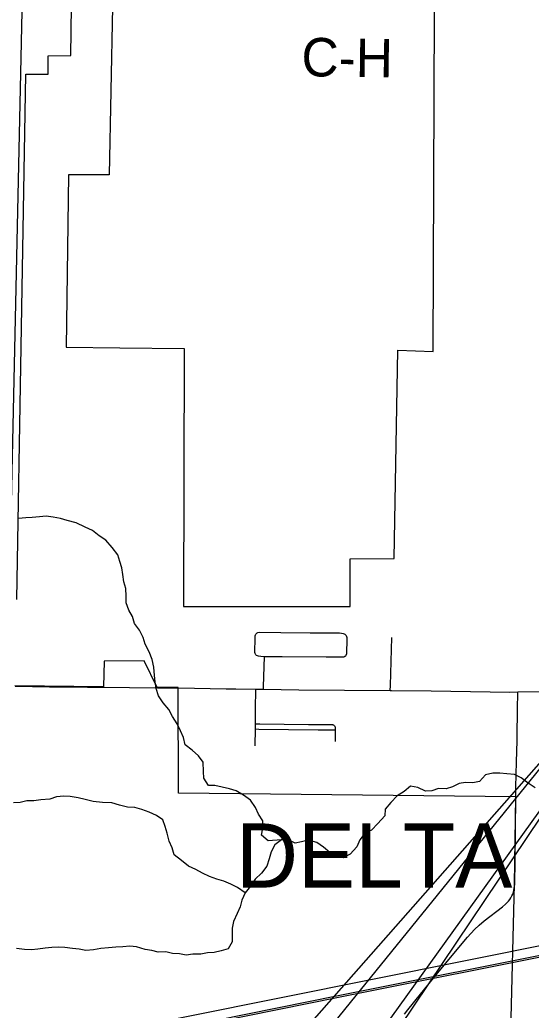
# Model space of a CAD drawing. Extents: x -21.7 to 34, y 0 to 22.
# Drawn here: x 25.914 to 26.67, y 17.008 to 18.47 of the extents above; entities that cross this region are included whole.
import ezdxf

# ---------------------------------------------------------------- set-up
doc = ezdxf.new("R2010")
doc.units = 0
for name, color, linetype in [('GM_X_City_Street', 7, 'Continuous'), ('GM_X_Corporation', 7, 'Continuous'), ('GM_X_Corporation_Text', 7, 'Continuous'), ('GM_X_County_Road', 7, 'Continuous'), ('GM_X_County_Road_Text', 7, 'Continuous'), ('GM_X_Minor_River', 7, 'Continuous'), ('GM_X_Rail_Line', 7, 'Continuous'), ('GM_X_State_Route', 7, 'Continuous'), ('GM_X_US_Route', 7, 'Continuous'), ('SH_Text', 7, 'Continuous')]:
    doc.layers.add(name, color=color, linetype=linetype)

msp = doc.modelspace()

# ---------------------------------------------------------------- linework, layer by layer
at = {"layer": 'GM_X_City_Street'}
msp.add_line((26.2622, 17.3982), (26.2624, 17.4229), dxfattribs=at)
for points in [[(26.2759, 17.5296), (26.2703, 17.5299), (26.267, 17.5305), (26.2655, 17.5309), (26.2641, 17.5315), (26.2632, 17.5323), (26.2625, 17.5333), (26.2619, 17.5345), (26.2617, 17.5356), (26.2615, 17.5373), (26.2614, 17.5403), (26.2618, 17.5529), (26.262, 17.559), (26.2622, 17.5605), (26.2626, 17.5619), (26.2631, 17.563), (26.2639, 17.5641), (26.2647, 17.5648), (26.266, 17.5654), (26.2688, 17.5658), (26.2998, 17.5655), (26.3432, 17.5649), (26.3772, 17.5647), (26.3865, 17.5648), (26.3896, 17.5646), (26.3922, 17.5641), (26.3934, 17.5636), (26.3944, 17.5629), (26.3962, 17.5608), (26.3968, 17.5596), (26.3972, 17.5582), (26.3974, 17.5551), (26.3969, 17.535), (26.3967, 17.5334), (26.3966, 17.5327), (26.3961, 17.5314), (26.3952, 17.5304), (26.3944, 17.5297), (26.393, 17.5291), (26.3917, 17.5289), (26.3887, 17.5288), (26.367, 17.5289), (26.3021, 17.5294), (26.2759, 17.5296)], [(26.4615, 17.4797), (26.4617, 17.4869), (26.4639, 17.558)], [(26.2741, 17.4816), (26.2742, 17.4856), (26.2759, 17.5296)], [(26.2625, 17.4305), (26.2627, 17.4578), (26.2629, 17.4763), (26.2629, 17.4818)], [(26.2624, 17.4229), (26.2625, 17.4238), (26.2625, 17.4305)], [(26.2625, 17.4305), (26.2691, 17.4304), (26.3409, 17.4296), (26.3753, 17.4295), (26.3762, 17.4294), (26.3768, 17.4292), (26.3776, 17.4289), (26.3782, 17.4285), (26.3788, 17.428), (26.3793, 17.4274), (26.3797, 17.4267), (26.38, 17.4261), (26.3802, 17.4253), (26.3803, 17.4245), (26.3804, 17.423), (26.3804, 17.4217)], [(26.2624, 17.4229), (26.2672, 17.4228), (26.3553, 17.4217), (26.3742, 17.4217), (26.3804, 17.4217)], [(26.3804, 17.4217), (26.3803, 17.4199), (26.3802, 17.4043)]]:
    msp.add_lwpolyline(points, dxfattribs=at)
at = {"layer": 'GM_X_Corporation'}
for points in [[(25.9101, 17.6139), (25.9163, 17.9873), (25.9231, 18.3896), (25.956, 18.3896), (25.9564, 18.4169), (25.9895, 18.4172), (25.9908, 18.4897)], [(26.0513, 18.4893), (26.0461, 18.2409), (25.9862, 18.2409), (25.9829, 17.9866), (26.062, 17.9857), (26.1572, 17.9846), (26.1563, 17.6036), (26.4021, 17.6038), (26.4021, 17.6743), (26.4675, 17.6744), (26.4727, 17.982), (26.5248, 17.9802), (26.527, 18.482)], [(26.6397, 16.9761), (26.6452, 17.1938), (26.6469, 17.3226), (26.1489, 17.3283), (26.1483, 17.4841), (26.1174, 17.4842), (26.098, 17.5236), (26.0387, 17.5231), (26.0379, 17.485), (25.9072, 17.4864)]]:
    msp.add_lwpolyline(points, dxfattribs=at)
at = {"layer": 'GM_X_County_Road'}
for points in [[(26.6471, 17.322), (26.6472, 17.337), (26.6481, 17.3743), (26.6489, 17.4054), (26.6496, 17.4582), (26.6499, 17.4707), (26.6501, 17.4776)], [(26.6455, 17.1932), (26.6457, 17.1971), (26.6462, 17.2251), (26.6471, 17.322)], [(26.4827, 17.0017), (26.4876, 17.0083), (26.5063, 17.0315), (26.532, 17.0627), (26.5557, 17.0916), (26.5758, 17.1154), (26.5862, 17.1269), (26.593, 17.1334), (26.6001, 17.1395), (26.6272, 17.1604), (26.6319, 17.1645), (26.6361, 17.1689), (26.638, 17.1713), (26.6397, 17.1738), (26.6412, 17.1764), (26.6424, 17.1792), (26.6435, 17.182), (26.6443, 17.185), (26.6453, 17.191), (26.6455, 17.1932)]]:
    msp.add_lwpolyline(points, dxfattribs=at)
at = {"layer": 'GM_X_Minor_River'}
for points in [[(26.3007, 17.2591), (26.281, 17.2577), (26.2713, 17.2662), (26.2731, 17.2764), (26.2733, 17.2871), (26.2671, 17.2971), (26.2624, 17.307), (26.2551, 17.3178), (26.245, 17.3253), (26.2341, 17.3316), (26.2243, 17.3345), (26.2024, 17.3395), (26.193, 17.3397), (26.186, 17.3501), (26.1855, 17.36), (26.1854, 17.3737), (26.1784, 17.3833), (26.1688, 17.3915), (26.1587, 17.3997), (26.1559, 17.4104), (26.1516, 17.42), (26.1469, 17.4303), (26.14, 17.4415), (26.1345, 17.4515), (26.126, 17.4615), (26.1194, 17.4719), (26.1159, 17.4826), (26.1142, 17.4925), (26.1133, 17.5021), (26.1121, 17.5142), (26.1097, 17.5253), (26.1054, 17.5368), (26.0996, 17.5479), (26.0964, 17.5582), (26.0913, 17.569), (26.0836, 17.5786), (26.0808, 17.5889), (26.0753, 17.5985), (26.0714, 17.6093), (26.0713, 17.6188), (26.0708, 17.6302), (26.068, 17.6401), (26.0663, 17.6511), (26.065, 17.6606), (26.0622, 17.6702), (26.059, 17.6798), (26.0506, 17.691), (26.0413, 17.7018), (26.0316, 17.7081), (26.0216, 17.7159), (26.0107, 17.7211), (25.9975, 17.7271), (25.9843, 17.7308), (25.9742, 17.7337), (25.9636, 17.7354), (25.9534, 17.7372), (25.9435, 17.7362), (25.9328, 17.735), (25.923, 17.7348), (25.9123, 17.7335)], [(26.6755, 17.3358), (26.6654, 17.3428), (26.655, 17.3506), (26.6452, 17.3558), (26.6338, 17.3568), (26.6236, 17.3578), (26.613, 17.3576), (26.6023, 17.3552), (26.5934, 17.3456), (26.5835, 17.3435), (26.5728, 17.3441), (26.5633, 17.3424), (26.5537, 17.3377), (26.5442, 17.3345), (26.5328, 17.3348), (26.5229, 17.3316), (26.5134, 17.331), (26.5021, 17.3366), (26.4915, 17.3384), (26.4819, 17.3306), (26.4718, 17.3244), (26.4625, 17.3143), (26.4539, 17.3047), (26.4533, 17.2948), (26.4432, 17.2836), (26.4339, 17.2736), (26.4243, 17.2696), (26.4165, 17.2592), (26.412, 17.2487), (26.4023, 17.2382), (26.3919, 17.2328), (26.3821, 17.2353), (26.3724, 17.2404), (26.3627, 17.2482), (26.353, 17.2553), (26.3406, 17.259), (26.3306, 17.2562), (26.3211, 17.2545)], [(26.2473, 17.181), (26.236, 17.1888), (26.226, 17.1936), (26.2158, 17.198), (26.2053, 17.2013), (26.1944, 17.2053), (26.1843, 17.2101), (26.1741, 17.2153), (26.1633, 17.2204), (26.1532, 17.2286), (26.1424, 17.2372), (26.1396, 17.2475), (26.1349, 17.2575), (26.1321, 17.269), (26.1289, 17.2789), (26.1258, 17.2888), (26.116, 17.2951), (26.1055, 17.2999), (26.0946, 17.304), (26.0841, 17.3069), (26.0735, 17.3075), (26.0618, 17.3104), (26.0501, 17.3137), (26.0364, 17.3144), (26.0228, 17.3158), (26.0111, 17.3187), (26.0006, 17.3212), (25.9889, 17.3234), (25.9794, 17.3236), (25.9683, 17.3227), (25.9588, 17.3195), (25.9455, 17.3183), (25.9352, 17.317), (25.9246, 17.3169), (25.9147, 17.3144), (25.9048, 17.3139)], [(26.3211, 17.2545), (26.311, 17.2593), (26.3007, 17.2591), (26.2911, 17.2521), (26.2855, 17.2416), (26.2826, 17.2311), (26.2793, 17.2205), (26.2715, 17.21), (26.2618, 17.2012), (26.2551, 17.1907), (26.2473, 17.181), (26.2425, 17.1701), (26.2396, 17.1603), (26.2352, 17.1505), (26.23, 17.1389), (26.2279, 17.1287), (26.228, 17.118), (26.2282, 17.1085), (26.2219, 17.0984), (26.2116, 17.0952), (26.2016, 17.0928), (26.1914, 17.0923), (26.1815, 17.0902), (26.1701, 17.0905), (26.1602, 17.0888), (26.1504, 17.0909), (26.1401, 17.0915), (26.1299, 17.0937), (26.1189, 17.0935), (26.1091, 17.096), (26.0993, 17.0974), (26.0869, 17.1015), (26.0767, 17.1024), (26.0664, 17.1011), (26.0561, 17.101), (26.0455, 17.0997), (26.0341, 17.0988), (26.023, 17.0968), (26.012, 17.0959), (26.0022, 17.0977), (25.992, 17.0986), (25.981, 17.1004), (25.9715, 17.1006), (25.9617, 17.1005), (25.9518, 17.0995), (25.9411, 17.0979), (25.9316, 17.097), (25.921, 17.0972), (25.9093, 17.0986)]]:
    msp.add_lwpolyline(points, dxfattribs=at)
at = {"layer": 'GM_X_Rail_Line'}
for points in [[(25.8368, 14.1), (25.8424, 14.4841), (25.8672, 15.4825), (25.8776, 16.2603), (25.8795, 16.4862), (25.8906, 16.927), (25.8907, 16.9438), (25.8961, 17.4845), (25.9239, 18.7551), (25.935, 19.5978), (25.9554, 20.5461), (25.9616, 20.9)], [(25.8905, 16.9443), (26.7077, 17.1083), (26.7688, 17.1586), (26.8119, 17.2101), (26.8634, 17.276), (26.8946, 17.3324), (26.9509, 17.3923), (27.006, 17.4474), (27.0347, 17.4689), (27.0802, 17.4809), (27.5534, 17.4838), (27.9584, 17.4827), (28.1647, 17.4796), (28.575, 17.4796), (29.0617, 17.5773), (30.0904, 17.7802), (30.3167, 17.8248)], [(23.5167, 16.459), (23.6295, 16.4808), (23.9621, 16.5465), (24.6321, 16.6797), (25.2774, 16.8081), (25.8901, 16.9293), (26.3845, 17.0293), (27.0776, 17.1675), (27.7467, 17.2984), (28.3715, 17.4275), (28.9889, 17.5495), (29.6221, 17.6814), (30.2791, 17.8098), (30.3167, 17.8172)], [(23.5167, 16.4567), (23.6289, 16.4784), (23.9619, 16.5433), (24.6317, 16.6775), (25.2779, 16.8058), (25.8906, 16.927), (26.3849, 17.0271), (27.078, 17.1653), (27.7471, 17.2961), (28.3719, 17.4252), (28.9894, 17.5472), (29.6225, 17.6791), (30.2796, 17.8076), (30.3167, 17.8149)]]:
    msp.add_lwpolyline(points, dxfattribs=at)
at = {"layer": 'GM_X_State_Route'}
for p, q in [((26.1176, 17.4837), (26.1486, 17.4836)), ((26.1486, 17.4836), (26.2192, 17.4824)), ((26.2629, 17.4818), (26.2741, 17.4816))]:
    msp.add_line(p, q, dxfattribs=at)
for points in [[(25.9074, 17.4859), (25.9581, 17.4852), (26.0141, 17.4848), (26.0381, 17.4845)], [(26.0381, 17.4845), (26.0763, 17.484), (26.1176, 17.4837)], [(26.2192, 17.4824), (26.2333, 17.4822), (26.2629, 17.4818)], [(26.2741, 17.4816), (26.3265, 17.4809), (26.4615, 17.4797)], [(26.4615, 17.4797), (26.4632, 17.4797), (26.5222, 17.4791), (26.6091, 17.4778), (26.6371, 17.4775), (26.6501, 17.4776)], [(26.6501, 17.4776), (26.699, 17.4781), (26.7792, 17.4787)]]:
    msp.add_lwpolyline(points, dxfattribs=at)
at = {"layer": 'GM_X_US_Route'}
for p, q in [((26.1176, 17.4837), (26.1486, 17.4836)), ((26.1486, 17.4836), (26.2192, 17.4824)), ((26.2629, 17.4818), (26.2741, 17.4816))]:
    msp.add_line(p, q, dxfattribs=at)
for points in [[(25.9074, 17.4859), (25.9581, 17.4852), (26.0141, 17.4848), (26.0381, 17.4845)], [(26.0381, 17.4845), (26.0763, 17.484), (26.1176, 17.4837)], [(26.2192, 17.4824), (26.2333, 17.4822), (26.2629, 17.4818)], [(26.2741, 17.4816), (26.3265, 17.4809), (26.4615, 17.4797)], [(26.4615, 17.4797), (26.4632, 17.4797), (26.5222, 17.4791), (26.6091, 17.4778), (26.6371, 17.4775), (26.6501, 17.4776)], [(26.6501, 17.4776), (26.699, 17.4781), (26.7792, 17.4787)]]:
    msp.add_lwpolyline(points, dxfattribs=at)
at = {"layer": 'SH_Text'}
for points in [[(23.5845, 13.5445), (26.7756, 17.4787), (23.5845, 13.8593)], [(23.5845, 12.6836), (26.8092, 17.4787), (23.5845, 12.9954)]]:
    msp.add_lwpolyline(points, close=True, dxfattribs=at)

# ---------------------------------------------------------------- texts
at = {"layer": 'GM_X_Corporation_Text'}
msp.add_text('DELTA', height=0.0947, rotation=0, dxfattribs=at).set_placement((26.2338, 17.1888))
at = {"layer": 'GM_X_County_Road_Text'}
msp.add_text('C-H', height=0.05682, rotation=359.2083, dxfattribs=at).set_placement((26.3301, 18.3867))

doc.saveas('drawing.dxf')
